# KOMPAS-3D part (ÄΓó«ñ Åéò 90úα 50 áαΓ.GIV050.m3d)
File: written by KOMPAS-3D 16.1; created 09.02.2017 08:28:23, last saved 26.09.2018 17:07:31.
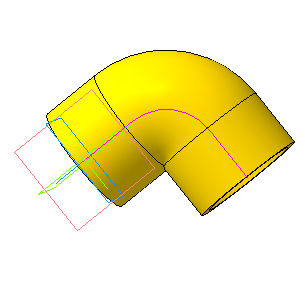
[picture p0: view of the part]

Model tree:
1. Эскиз:1
2. Эскиз:24
3. Кинематическая операция:1
4. Эскиз:25
5. Вырезать кинематический элемент:1
6. Эскиз:26
7. Вырезать элемент выдавливания:9
     Расстояние 1 = 31
8. Эскиз:27
9. Вырезать элемент выдавливания:10
     Расстояние 1 = 31

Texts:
  Отвод ПВХ 90гр 50 арт.GIV050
